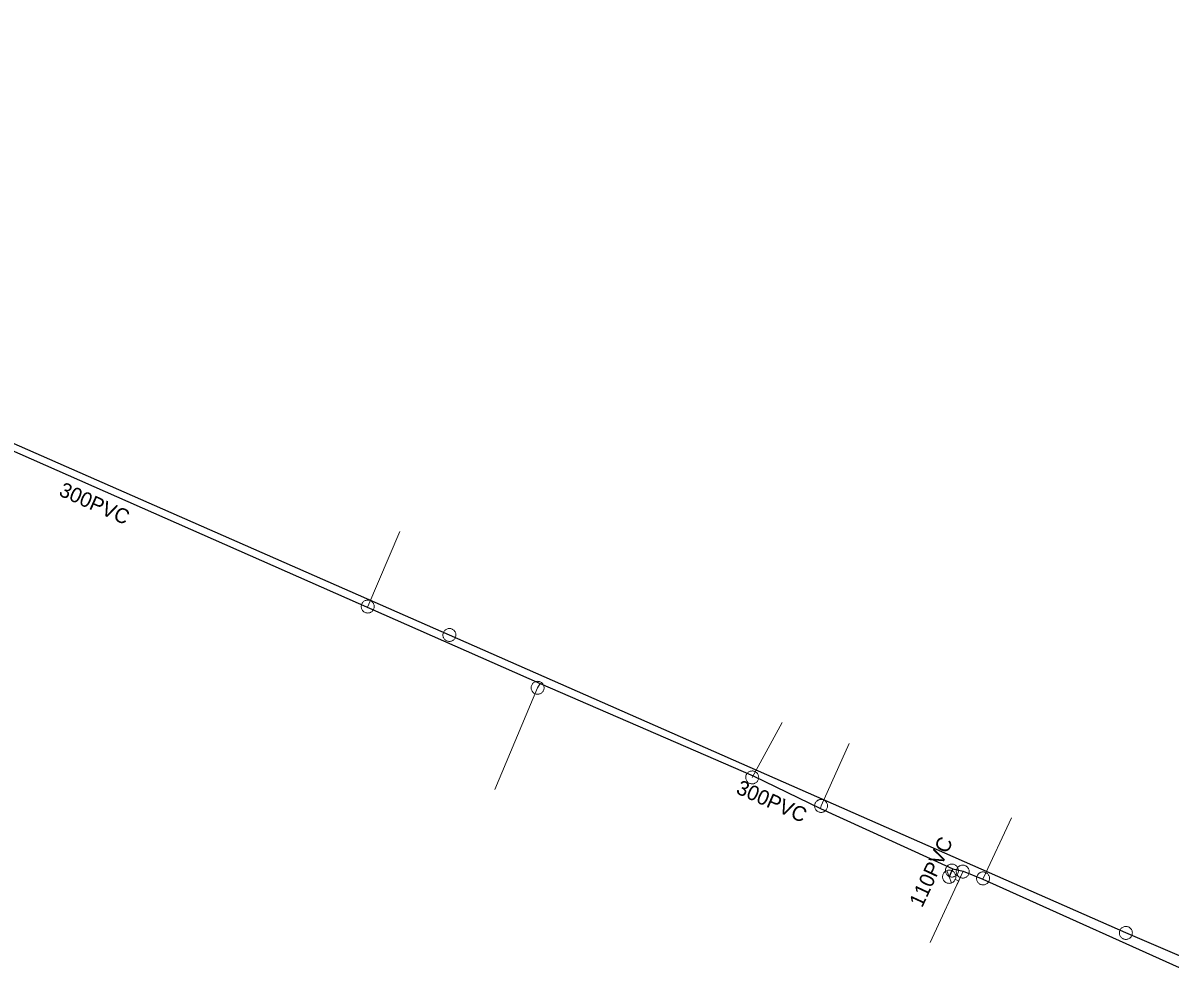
# Model space of a CAD drawing. Extents: x -741806 to -738704, y -1059275 to -1055387.
# Drawn here: x -740567.1 to -740489.7, y -1058133.8 to -1058069.3 of the extents above; entities that cross this region are included whole.
import ezdxf

# ---------------------------------------------------------------- set-up
doc = ezdxf.new("R2010")
doc.units = 0
doc.header["$LTSCALE"] = 0.4
for name, color, linetype, lineweight in [('2', 7, 'Continuous', 25), ('21', 7, 'Continuous', 13), ('3', 7, 'Continuous', 13), ('50', 7, 'Continuous', 13), ('51', 7, 'Continuous', 13), ('52', 7, 'Continuous', 25)]:
    doc.layers.add(name, color=color, linetype=linetype, lineweight=lineweight)
doc.layers.add('5', color=7, linetype='Continuous')
doc.layers.add('53', color=7, linetype='Continuous')

msp = doc.modelspace()

# ---------------------------------------------------------------- linework, layer by layer
at = {"layer": '2'}
for p, q in [((-740538.35, -1058110.56), (-740584.07, -1058090.47)), ((-740492.73, -1058130.659), (-740538.35, -1058110.56)), ((-740451.32, -1058148.44), (-740492.73, -1058130.659))]:
    msp.add_line(p, q, dxfattribs=at)
at = {"layer": '21'}
for p, q in [((-740517.93, -1058120.169), (-740515.916, -1058116.469)), ((-740503.699, -1058126.483), (-740505.938, -1058131.308))]:
    msp.add_line(p, q, dxfattribs=at)
for points in [[(-740543.865, -1058108.693), (-740543.859, -1058108.639), (-740541.684, -1058103.585)], [(-740532.225, -1058113.83), (-740532.399, -1058114.12), (-740535.282, -1058120.975)], [(-740513.324, -1058122.253), (-740513.289, -1058122.09), (-740511.392, -1058117.872)], [(-740502.37, -1058127.033), (-740502.359, -1058126.98), (-740500.445, -1058122.891)]]:
    msp.add_lwpolyline(points, dxfattribs=at)
at = {"layer": '3'}
msp.add_lwpolyline([(-740538.75, -1058110.382), (-740538.766, -1058110.425), (-740538.777, -1058110.469), (-740538.784, -1058110.515), (-740538.787, -1058110.56), (-740538.784, -1058110.606), (-740538.777, -1058110.651), (-740538.764, -1058110.695), (-740538.748, -1058110.738), (-740538.727, -1058110.778), (-740538.702, -1058110.817), (-740538.673, -1058110.852), (-740538.641, -1058110.885), (-740538.605, -1058110.913), (-740538.567, -1058110.939), (-740538.525, -1058110.959), (-740538.483, -1058110.976), (-740538.438, -1058110.986), (-740538.393, -1058110.994), (-740538.347, -1058110.996), (-740538.301, -1058110.993), (-740538.256, -1058110.986), (-740538.213, -1058110.974), (-740538.17, -1058110.957), (-740538.129, -1058110.937), (-740538.09, -1058110.911), (-740538.056, -1058110.882), (-740538.023, -1058110.85), (-740537.994, -1058110.814), (-740537.969, -1058110.776), (-740537.949, -1058110.734), (-740537.933, -1058110.692), (-740537.921, -1058110.648), (-740537.914, -1058110.602), (-740537.912, -1058110.556), (-740537.914, -1058110.511), (-740537.921, -1058110.466), (-740537.934, -1058110.422), (-740537.951, -1058110.378), (-740537.971, -1058110.339), (-740537.996, -1058110.301), (-740538.025, -1058110.265), (-740538.058, -1058110.232), (-740538.093, -1058110.203), (-740538.131, -1058110.179), (-740538.173, -1058110.158), (-740538.216, -1058110.142), (-740538.26, -1058110.13), (-740538.305, -1058110.123), (-740538.351, -1058110.121), (-740538.397, -1058110.124), (-740538.442, -1058110.131), (-740538.486, -1058110.143), (-740538.529, -1058110.16), (-740538.569, -1058110.18), (-740538.608, -1058110.206), (-740538.644, -1058110.235), (-740538.675, -1058110.267), (-740538.704, -1058110.303), (-740538.729, -1058110.342)], close=True, dxfattribs=at)
msp.add_lwpolyline([(-740493.132, -1058130.485), (-740493.147, -1058130.528), (-740493.158, -1058130.572), (-740493.165, -1058130.618), (-740493.167, -1058130.663), (-740493.164, -1058130.709), (-740493.156, -1058130.755), (-740493.143, -1058130.798), (-740493.127, -1058130.841), (-740493.105, -1058130.881), (-740493.08, -1058130.919), (-740493.05, -1058130.954), (-740493.017, -1058130.987), (-740492.981, -1058131.014), (-740492.943, -1058131.04), (-740492.902, -1058131.06), (-740492.859, -1058131.076), (-740492.814, -1058131.086), (-740492.769, -1058131.094), (-740492.723, -1058131.095), (-740492.677, -1058131.092), (-740492.632, -1058131.084), (-740492.589, -1058131.072), (-740492.546, -1058131.055), (-740492.505, -1058131.034), (-740492.467, -1058131.008), (-740492.433, -1058130.978), (-740492.4, -1058130.946), (-740492.372, -1058130.91), (-740492.347, -1058130.871), (-740492.327, -1058130.83), (-740492.311, -1058130.787), (-740492.3, -1058130.743), (-740492.293, -1058130.697), (-740492.292, -1058130.651), (-740492.295, -1058130.606), (-740492.302, -1058130.561), (-740492.315, -1058130.517), (-740492.332, -1058130.474), (-740492.353, -1058130.434), (-740492.379, -1058130.396), (-740492.408, -1058130.361), (-740492.441, -1058130.328), (-740492.476, -1058130.3), (-740492.515, -1058130.276), (-740492.556, -1058130.256), (-740492.6, -1058130.239), (-740492.644, -1058130.228), (-740492.689, -1058130.222), (-740492.735, -1058130.22), (-740492.781, -1058130.223), (-740492.826, -1058130.231), (-740492.87, -1058130.243), (-740492.912, -1058130.261), (-740492.953, -1058130.281), (-740492.991, -1058130.307), (-740493.027, -1058130.337), (-740493.058, -1058130.369), (-740493.087, -1058130.406), (-740493.111, -1058130.444), (-740493.131, -1058130.484)], dxfattribs=at)
at = {"layer": '50'}
for p, q in [((-740504.644, -1058126.868), (-740504.81, -1058126.451)), ((-740504.644, -1058126.868), (-740504.481, -1058127.28)), ((-740504.232, -1058127.043), (-740504.002, -1058127.142)), ((-740504.123, -1058127.424), (-740504.002, -1058127.142)), ((-740503.88, -1058126.859), (-740504.002, -1058127.142))]:
    msp.add_line(p, q, dxfattribs=at)
msp.add_lwpolyline([(-740504.822, -1058127.274), (-740504.776, -1058127.291), (-740504.732, -1058127.304), (-740504.684, -1058127.31), (-740504.638, -1058127.312), (-740504.594, -1058127.31), (-740504.546, -1058127.301), (-740504.502, -1058127.289), (-740504.457, -1058127.272), (-740504.415, -1058127.252), (-740504.378, -1058127.224), (-740504.341, -1058127.195), (-740504.307, -1058127.163), (-740504.28, -1058127.125), (-740504.254, -1058127.086), (-740504.233, -1058127.045), (-740504.218, -1058127.001), (-740504.205, -1058126.958), (-740504.199, -1058126.911), (-740504.197, -1058126.863), (-740504.199, -1058126.816), (-740504.207, -1058126.771), (-740504.219, -1058126.725), (-740504.237, -1058126.682), (-740504.257, -1058126.642), (-740504.283, -1058126.601), (-740504.312, -1058126.565), (-740504.346, -1058126.533), (-740504.382, -1058126.502), (-740504.423, -1058126.479), (-740504.463, -1058126.456), (-740504.508, -1058126.44), (-740504.553, -1058126.429), (-740504.597, -1058126.422), (-740504.646, -1058126.419), (-740504.692, -1058126.423), (-740504.738, -1058126.429), (-740504.782, -1058126.443), (-740504.827, -1058126.458), (-740504.87, -1058126.481), (-740504.907, -1058126.507), (-740504.944, -1058126.538), (-740504.976, -1058126.571), (-740505.005, -1058126.605), (-740505.032, -1058126.647), (-740505.053, -1058126.688), (-740505.068, -1058126.731), (-740505.079, -1058126.777), (-740505.087, -1058126.823), (-740505.089, -1058126.869), (-740505.086, -1058126.917), (-740505.079, -1058126.962), (-740505.066, -1058127.009), (-740505.05, -1058127.051), (-740505.029, -1058127.092), (-740505.001, -1058127.13), (-740504.974, -1058127.168), (-740504.94, -1058127.201), (-740504.902, -1058127.228), (-740504.863, -1058127.253)], close=True, dxfattribs=at)
at = {"layer": '51'}
for points in [[(-740543.812, -1058108.204), (-740543.857, -1058108.201), (-740543.902, -1058108.203), (-740543.948, -1058108.211), (-740543.992, -1058108.222), (-740544.035, -1058108.239), (-740544.076, -1058108.259), (-740544.114, -1058108.285), (-740544.15, -1058108.313), (-740544.182, -1058108.346), (-740544.211, -1058108.381), (-740544.236, -1058108.42), (-740544.257, -1058108.46), (-740544.274, -1058108.503), (-740544.286, -1058108.547), (-740544.293, -1058108.593), (-740544.295, -1058108.638), (-740544.293, -1058108.684), (-740544.286, -1058108.729), (-740544.274, -1058108.774), (-740544.257, -1058108.817), (-740544.236, -1058108.857), (-740544.212, -1058108.896), (-740544.183, -1058108.931), (-740544.151, -1058108.964), (-740544.115, -1058108.992), (-740544.076, -1058109.018), (-740544.036, -1058109.038), (-740543.993, -1058109.055), (-740543.949, -1058109.066), (-740543.903, -1058109.074), (-740543.858, -1058109.076), (-740543.813, -1058109.074), (-740543.767, -1058109.067), (-740543.723, -1058109.055), (-740543.68, -1058109.039), (-740543.639, -1058109.018), (-740543.601, -1058108.993), (-740543.565, -1058108.964), (-740543.533, -1058108.931), (-740543.504, -1058108.896), (-740543.479, -1058108.858), (-740543.458, -1058108.817), (-740543.442, -1058108.774), (-740543.429, -1058108.73), (-740543.422, -1058108.685), (-740543.42, -1058108.639), (-740543.423, -1058108.593), (-740543.429, -1058108.548), (-740543.441, -1058108.504), (-740543.458, -1058108.461), (-740543.479, -1058108.42), (-740543.503, -1058108.382), (-740543.532, -1058108.346), (-740543.564, -1058108.314), (-740543.6, -1058108.285), (-740543.639, -1058108.26), (-740543.679, -1058108.239), (-740543.722, -1058108.223), (-740543.766, -1058108.211), (-740543.811, -1058108.204)], [(-740531.962, -1058114.12), (-740531.963, -1058114.075), (-740531.971, -1058114.03), (-740531.983, -1058113.985), (-740531.999, -1058113.943), (-740532.02, -1058113.902), (-740532.044, -1058113.863), (-740532.074, -1058113.828), (-740532.106, -1058113.795), (-740532.142, -1058113.767), (-740532.179, -1058113.742), (-740532.221, -1058113.721), (-740532.264, -1058113.704), (-740532.308, -1058113.692), (-740532.353, -1058113.685), (-740532.399, -1058113.683), (-740532.445, -1058113.685), (-740532.49, -1058113.692), (-740532.534, -1058113.704), (-740532.576, -1058113.721), (-740532.618, -1058113.742), (-740532.656, -1058113.767), (-740532.691, -1058113.795), (-740532.723, -1058113.828), (-740532.753, -1058113.863), (-740532.777, -1058113.902), (-740532.799, -1058113.943), (-740532.815, -1058113.985), (-740532.826, -1058114.03), (-740532.834, -1058114.075), (-740532.837, -1058114.121), (-740532.834, -1058114.166), (-740532.826, -1058114.211), (-740532.815, -1058114.256), (-740532.799, -1058114.298), (-740532.777, -1058114.339), (-740532.753, -1058114.378), (-740532.723, -1058114.413), (-740532.691, -1058114.446), (-740532.656, -1058114.474), (-740532.618, -1058114.499), (-740532.576, -1058114.52), (-740532.534, -1058114.537), (-740532.49, -1058114.548), (-740532.445, -1058114.556), (-740532.399, -1058114.558), (-740532.353, -1058114.556), (-740532.308, -1058114.548), (-740532.264, -1058114.537), (-740532.221, -1058114.52), (-740532.179, -1058114.499), (-740532.142, -1058114.474), (-740532.106, -1058114.446), (-740532.074, -1058114.413), (-740532.044, -1058114.378), (-740532.02, -1058114.339), (-740531.999, -1058114.298), (-740531.983, -1058114.256), (-740531.971, -1058114.211), (-740531.963, -1058114.166), (-740531.962, -1058114.121)], [(-740517.72, -1058119.785), (-740517.761, -1058119.765), (-740517.804, -1058119.75), (-740517.849, -1058119.739), (-740517.893, -1058119.733), (-740517.939, -1058119.732), (-740517.986, -1058119.735), (-740518.03, -1058119.744), (-740518.075, -1058119.756), (-740518.116, -1058119.774), (-740518.156, -1058119.796), (-740518.195, -1058119.822), (-740518.23, -1058119.851), (-740518.262, -1058119.884), (-740518.289, -1058119.92), (-740518.313, -1058119.96), (-740518.333, -1058120.001), (-740518.349, -1058120.044), (-740518.359, -1058120.089), (-740518.365, -1058120.134), (-740518.366, -1058120.181), (-740518.362, -1058120.226), (-740518.355, -1058120.271), (-740518.341, -1058120.315), (-740518.324, -1058120.357), (-740518.302, -1058120.398), (-740518.276, -1058120.436), (-740518.246, -1058120.47), (-740518.213, -1058120.502), (-740518.176, -1058120.529), (-740518.137, -1058120.554), (-740518.096, -1058120.573), (-740518.054, -1058120.588), (-740518.008, -1058120.599), (-740517.964, -1058120.605), (-740517.918, -1058120.606), (-740517.872, -1058120.603), (-740517.827, -1058120.594), (-740517.783, -1058120.582), (-740517.741, -1058120.564), (-740517.701, -1058120.542), (-740517.663, -1058120.516), (-740517.627, -1058120.487), (-740517.597, -1058120.453), (-740517.568, -1058120.417), (-740517.544, -1058120.378), (-740517.524, -1058120.337), (-740517.51, -1058120.293), (-740517.498, -1058120.249), (-740517.493, -1058120.203), (-740517.491, -1058120.157), (-740517.495, -1058120.112), (-740517.503, -1058120.067), (-740517.516, -1058120.023), (-740517.533, -1058119.981), (-740517.556, -1058119.94), (-740517.582, -1058119.902), (-740517.611, -1058119.868), (-740517.645, -1058119.836), (-740517.681, -1058119.809), (-740517.719, -1058119.785)], [(-740513.199, -1058121.662), (-740513.243, -1058121.655), (-740513.289, -1058121.652), (-740513.335, -1058121.655), (-740513.38, -1058121.662), (-740513.424, -1058121.674), (-740513.467, -1058121.691), (-740513.507, -1058121.712), (-740513.546, -1058121.736), (-740513.581, -1058121.766), (-740513.613, -1058121.798), (-740513.642, -1058121.834), (-740513.668, -1058121.873), (-740513.688, -1058121.913), (-740513.704, -1058121.956), (-740513.716, -1058122), (-740513.723, -1058122.046), (-740513.726, -1058122.091), (-740513.723, -1058122.137), (-740513.715, -1058122.182), (-740513.703, -1058122.227), (-740513.686, -1058122.269), (-740513.666, -1058122.31), (-740513.64, -1058122.348), (-740513.612, -1058122.384), (-740513.579, -1058122.416), (-740513.543, -1058122.445), (-740513.505, -1058122.469), (-740513.464, -1058122.49), (-740513.421, -1058122.506), (-740513.376, -1058122.519), (-740513.332, -1058122.525), (-740513.286, -1058122.527), (-740513.24, -1058122.525), (-740513.195, -1058122.518), (-740513.151, -1058122.505), (-740513.108, -1058122.489), (-740513.068, -1058122.468), (-740513.029, -1058122.443), (-740512.994, -1058122.413), (-740512.962, -1058122.381), (-740512.933, -1058122.346), (-740512.907, -1058122.307), (-740512.888, -1058122.266), (-740512.871, -1058122.224), (-740512.859, -1058122.179), (-740512.852, -1058122.134), (-740512.85, -1058122.088), (-740512.852, -1058122.043), (-740512.86, -1058121.997), (-740512.872, -1058121.953), (-740512.889, -1058121.91), (-740512.909, -1058121.869), (-740512.935, -1058121.831), (-740512.963, -1058121.796), (-740512.996, -1058121.763), (-740513.032, -1058121.734), (-740513.07, -1058121.71), (-740513.112, -1058121.689), (-740513.154, -1058121.673), (-740513.198, -1058121.662)], [(-740504.693, -1058126.819), (-740504.654, -1058126.841), (-740504.612, -1058126.859), (-740504.568, -1058126.873), (-740504.524, -1058126.882), (-740504.478, -1058126.886), (-740504.431, -1058126.886), (-740504.386, -1058126.88), (-740504.341, -1058126.87), (-740504.298, -1058126.855), (-740504.257, -1058126.836), (-740504.217, -1058126.813), (-740504.18, -1058126.785), (-740504.146, -1058126.755), (-740504.117, -1058126.72), (-740504.09, -1058126.682), (-740504.067, -1058126.642), (-740504.049, -1058126.601), (-740504.036, -1058126.557), (-740504.027, -1058126.512), (-740504.023, -1058126.466), (-740504.024, -1058126.42), (-740504.029, -1058126.375), (-740504.04, -1058126.33), (-740504.054, -1058126.287), (-740504.073, -1058126.245), (-740504.097, -1058126.205), (-740504.124, -1058126.169), (-740504.155, -1058126.135), (-740504.19, -1058126.105), (-740504.227, -1058126.078), (-740504.267, -1058126.057), (-740504.309, -1058126.039), (-740504.353, -1058126.025), (-740504.397, -1058126.016), (-740504.443, -1058126.012), (-740504.489, -1058126.012), (-740504.534, -1058126.018), (-740504.579, -1058126.028), (-740504.622, -1058126.043), (-740504.664, -1058126.062), (-740504.703, -1058126.085), (-740504.741, -1058126.113), (-740504.773, -1058126.144), (-740504.804, -1058126.178), (-740504.83, -1058126.216), (-740504.853, -1058126.256), (-740504.87, -1058126.298), (-740504.885, -1058126.341), (-740504.893, -1058126.386), (-740504.897, -1058126.432), (-740504.896, -1058126.478), (-740504.892, -1058126.523), (-740504.881, -1058126.568), (-740504.867, -1058126.611), (-740504.847, -1058126.653), (-740504.824, -1058126.693), (-740504.797, -1058126.729), (-740504.765, -1058126.763), (-740504.731, -1058126.793), (-740504.694, -1058126.818)], [(-740503.302, -1058126.609), (-740503.295, -1058126.565), (-740503.292, -1058126.519), (-740503.295, -1058126.473), (-740503.302, -1058126.428), (-740503.314, -1058126.384), (-740503.331, -1058126.341), (-740503.352, -1058126.3), (-740503.376, -1058126.262), (-740503.406, -1058126.227), (-740503.438, -1058126.195), (-740503.474, -1058126.166), (-740503.513, -1058126.14), (-740503.553, -1058126.12), (-740503.596, -1058126.104), (-740503.64, -1058126.092), (-740503.686, -1058126.085), (-740503.731, -1058126.082), (-740503.777, -1058126.085), (-740503.822, -1058126.093), (-740503.867, -1058126.105), (-740503.909, -1058126.122), (-740503.95, -1058126.142), (-740503.988, -1058126.168), (-740504.024, -1058126.196), (-740504.056, -1058126.229), (-740504.085, -1058126.265), (-740504.109, -1058126.303), (-740504.13, -1058126.345), (-740504.146, -1058126.387), (-740504.159, -1058126.432), (-740504.165, -1058126.476), (-740504.167, -1058126.522), (-740504.165, -1058126.568), (-740504.158, -1058126.613), (-740504.145, -1058126.657), (-740504.129, -1058126.7), (-740504.108, -1058126.741), (-740504.083, -1058126.779), (-740504.053, -1058126.814), (-740504.021, -1058126.846), (-740503.985, -1058126.875), (-740503.947, -1058126.901), (-740503.906, -1058126.92), (-740503.864, -1058126.937), (-740503.819, -1058126.949), (-740503.774, -1058126.956), (-740503.728, -1058126.958), (-740503.683, -1058126.956), (-740503.637, -1058126.948), (-740503.593, -1058126.936), (-740503.55, -1058126.919), (-740503.509, -1058126.899), (-740503.471, -1058126.873), (-740503.436, -1058126.845), (-740503.403, -1058126.812), (-740503.374, -1058126.776), (-740503.35, -1058126.738), (-740503.329, -1058126.696), (-740503.313, -1058126.654), (-740503.302, -1058126.61)], [(-740502.277, -1058126.55), (-740502.322, -1058126.544), (-740502.367, -1058126.542), (-740502.414, -1058126.546), (-740502.458, -1058126.554), (-740502.502, -1058126.567), (-740502.545, -1058126.584), (-740502.585, -1058126.606), (-740502.623, -1058126.631), (-740502.657, -1058126.662), (-740502.689, -1058126.694), (-740502.717, -1058126.731), (-740502.742, -1058126.77), (-740502.762, -1058126.811), (-740502.777, -1058126.854), (-740502.787, -1058126.899), (-740502.794, -1058126.944), (-740502.795, -1058126.99), (-740502.792, -1058127.035), (-740502.783, -1058127.081), (-740502.77, -1058127.125), (-740502.753, -1058127.167), (-740502.732, -1058127.207), (-740502.705, -1058127.245), (-740502.676, -1058127.28), (-740502.642, -1058127.312), (-740502.606, -1058127.34), (-740502.568, -1058127.363), (-740502.526, -1058127.383), (-740502.483, -1058127.399), (-740502.438, -1058127.41), (-740502.393, -1058127.416), (-740502.348, -1058127.417), (-740502.301, -1058127.414), (-740502.257, -1058127.406), (-740502.213, -1058127.393), (-740502.17, -1058127.375), (-740502.13, -1058127.353), (-740502.092, -1058127.328), (-740502.058, -1058127.298), (-740502.026, -1058127.265), (-740501.998, -1058127.229), (-740501.973, -1058127.19), (-740501.954, -1058127.148), (-740501.938, -1058127.106), (-740501.928, -1058127.061), (-740501.921, -1058127.015), (-740501.921, -1058126.97), (-740501.923, -1058126.924), (-740501.932, -1058126.879), (-740501.945, -1058126.835), (-740501.962, -1058126.793), (-740501.983, -1058126.752), (-740502.01, -1058126.715), (-740502.039, -1058126.68), (-740502.073, -1058126.648), (-740502.109, -1058126.62), (-740502.147, -1058126.596), (-740502.189, -1058126.576), (-740502.232, -1058126.561), (-740502.276, -1058126.55)]]:
    msp.add_lwpolyline(points, dxfattribs=at)
at = {"layer": '52'}
for points in [[(-740626.537, -1058069.271), (-740611.274, -1058077.928), (-740607.048, -1058079.747), (-740579.795, -1058093.213), (-740570.602, -1058096.897), (-740532.225, -1058113.83), (-740517.855, -1058120.051), (-740513.324, -1058122.253), (-740504.39, -1058126.338), (-740503.699, -1058126.483), (-740502.37, -1058127.033), (-740486.897, -1058134.004), (-740457.162, -1058146.413), (-740443.484, -1058152.384), (-740427.182, -1058159.244), (-740419.138, -1058162.291), (-740410.995, -1058165.443), (-740391.353, -1058175.139), (-740386.026, -1058178.196), (-740381.706, -1058180.966), (-740367.603, -1058204.507), (-740360.942, -1058216.102), (-740348.353, -1058239.253)], [(-740504.39, -1058126.338), (-740504.46, -1058126.45), (-740504.64, -1058126.87)]]:
    msp.add_lwpolyline(points, dxfattribs=at)

# ---------------------------------------------------------------- texts
at = {"layer": '5'}
for p in [(-740564.754, -1058101.124), (-740519.084, -1058121.216)]:
    msp.add_text('300PVC', height=1, rotation=336, dxfattribs=at).set_placement(p)
at = {"layer": '53'}
msp.add_text('110PVC', height=1, rotation=65, dxfattribs=at).set_placement((-740506.472, -1058128.998))

doc.saveas('drawing.dxf')
